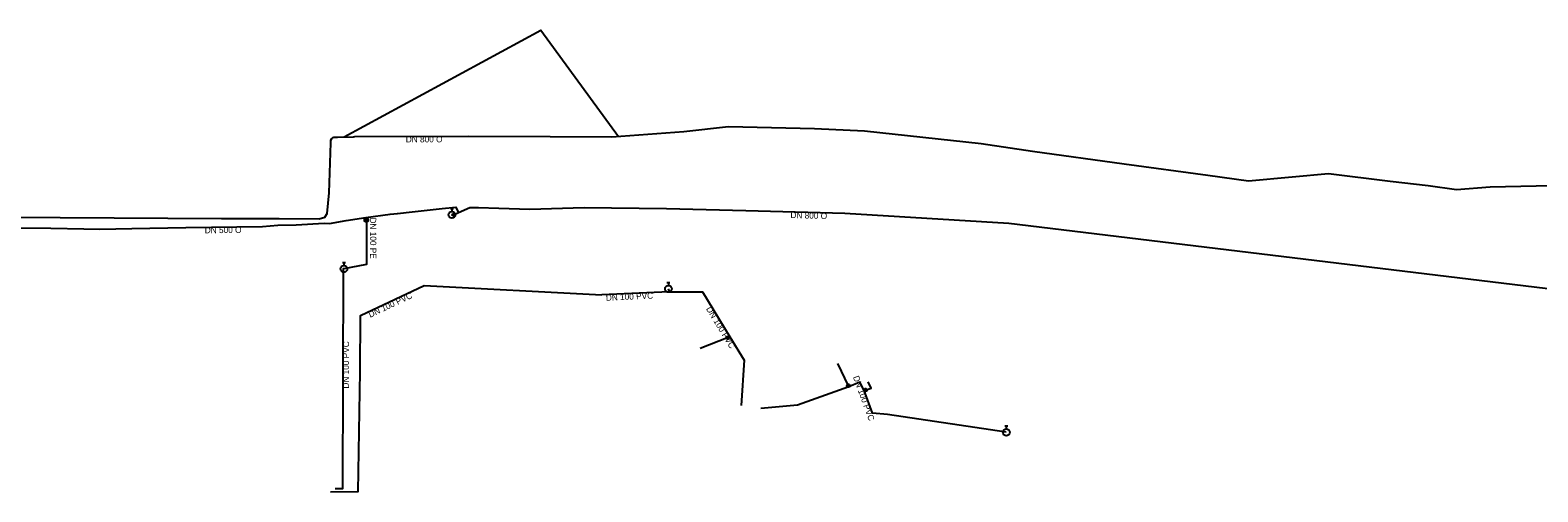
# Model space of a CAD drawing. Extents: x -451355 to -449353, y -1101368 to -1101089.
# Drawn here: x -450137.6 to -449745.7, y -1101299.4 to -1101179.4 of the extents above; entities that cross this region are included whole.
import ezdxf

# ---------------------------------------------------------------- set-up
doc = ezdxf.new("R2010")
doc.units = 0
for name, color, linetype in [('_hydrantova_odbocka_', 7, 'Continuous'), ('_pripojka_prevzato_z_dokumentace_', 7, 'Continuous'), ('_voda_projekt_smvak_', 7, 'Continuous'), ('_voda_smvak_prevzato_z_dokumentace_', 7, 'Continuous'), ('_voda_smvak_priblizne_', 7, 'Continuous'), ('Default', 7, 'Continuous'), ('MoLevel 2', 7, 'Continuous'), ('MoLevel 27', 7, 'Continuous'), ('MoLevel 28', 7, 'Continuous'), ('MoLevel 46', 7, 'Continuous'), ('MoLevel 53', 7, 'Continuous')]:
    doc.layers.add(name, color=color, linetype=linetype)

# ---------------------------------------------------------------- blocks, each defined once
blk = doc.blocks.new('_uzaver_')
at = {"layer": 'Default'}
for p, q in [((-0.000035, -0.000035), (0.000035, 0.000035)), ((0.000035, -0.000035), (-0.000035, 0.000035))]:
    blk.add_line(p, q, dxfattribs=at)
for radius in [0.00005, 0.0000025]:
    blk.add_circle((0, 0), radius, dxfattribs=at)
blk = doc.blocks.new('_uzaver_pripojka_')
at = {"layer": 'Default'}
for p, q in [((-0.000035, -0.000035), (0.000035, 0.000035)), ((0.000035, -0.000035), (-0.000035, 0.000035))]:
    blk.add_line(p, q, dxfattribs=at)
for radius in [0.00005, 0.0000025]:
    blk.add_circle((0, 0), radius, dxfattribs=at)
blk = doc.blocks.new('_hydrant_voda_')
at = {"layer": 'Default'}
for p, q in [((-0.000023, 0.000095), (0.000023, 0.000095)), ((0, 0.000095), (0, 0.00005))]:
    blk.add_line(p, q, dxfattribs=at)
blk.add_circle((0, 0), 0.00005, dxfattribs=at)

msp = doc.modelspace()

# ---------------------------------------------------------------- linework, layer by layer
at = {"layer": '_hydrantova_odbocka_'}
for points in [[(-450027.31, -1101227.36), (-450027.66, -1101227.39), (-450027.98, -1101227.39)], [(-449971.53, -1101247.37), (-449971.54, -1101247.14), (-449971.7, -1101246.64)]]:
    msp.add_lwpolyline(points, dxfattribs=at)
at = {"layer": '_pripojka_prevzato_z_dokumentace_'}
for points in [[(-449955.69, -1101259.11), (-449956.19, -1101259.31), (-449963.41, -1101262.16)], [(-449924.78, -1101272.09), (-449924.92, -1101271.81), (-449927.64, -1101266.02)], [(-449920.77, -1101273.05), (-449920.48, -1101272.96), (-449919.02, -1101272.44), (-449919.73, -1101270.78)]]:
    msp.add_lwpolyline(points, dxfattribs=at)
at = {"layer": '_voda_projekt_smvak_'}
msp.add_lwpolyline([(-450055.98, -1101207.15), (-450004.82, -1101179.37), (-449984.68, -1101207), (-449984.67, -1101207)], dxfattribs=at)
at = {"layer": '_voda_smvak_prevzato_z_dokumentace_'}
for p, q in [((-450026.26, -1101226.9), (-450027.31, -1101227.36)), ((-449971.53, -1101247.37), (-449989.04, -1101248.2))]:
    msp.add_line(p, q, dxfattribs=at)
for points in [[(-450157.79, -1101227.95), (-450087.83, -1101228.34), (-450072.87, -1101228.38), (-450062.45, -1101228.41), (-450060.97, -1101227.97), (-450060.37, -1101227.04), (-450059.89, -1101221.68), (-450059.42, -1101208.64), (-450059.44, -1101207.96), (-450059.16, -1101207.55), (-450058.95, -1101207.32), (-450058.66, -1101207.22), (-450057.69, -1101207.21), (-450053.58, -1101207.08), (-450053.2, -1101207.02), (-450023.78, -1101206.91), (-450002.42, -1101206.98), (-449986.4, -1101207.13), (-449967.71, -1101205.73), (-449956.08, -1101204.38), (-449933.75, -1101204.95), (-449920.75, -1101205.53), (-449890.41, -1101208.81), (-449877.09, -1101210.82), (-449853.21, -1101214.14), (-449831.47, -1101217.07), (-449820.94, -1101218.53), (-449809.59, -1101217.5), (-449800.08, -1101216.65), (-449784.1, -1101218.64), (-449774.23, -1101219.74), (-449766.81, -1101220.78), (-449758.11, -1101220.11), (-449738.15, -1101219.69)], [(-450050.32, -1101228.11), (-450044.02, -1101227.25), (-450042.09, -1101227), (-450038.31, -1101226.62), (-450030.47, -1101225.71), (-450026.99, -1101225.39), (-450026.26, -1101226.9)], [(-449564.49, -1101281.4), (-449698.07, -1101252.11), (-449883.18, -1101229.61), (-449925.88, -1101227.01), (-449951.55, -1101226.31), (-449972.21, -1101225.79), (-449993.64, -1101225.6), (-450007.68, -1101225.99), (-450015.78, -1101225.72), (-450021.06, -1101225.6), (-450023.29, -1101225.59), (-450026.26, -1101226.9)], [(-450157.74, -1101229.56), (-450149.08, -1101230.67), (-450142.79, -1101230.8), (-450132.2, -1101230.86), (-450123.68, -1101231), (-450119.47, -1101231.11), (-450111.15, -1101230.92), (-450097.13, -1101230.65), (-450077.24, -1101230.4), (-450073.21, -1101230.11), (-450068.42, -1101229.99), (-450061.21, -1101229.58), (-450059.76, -1101229.61), (-450055.48, -1101228.82), (-450050.32, -1101228.11)], [(-450056.05, -1101241.44), (-450056.28, -1101241.44), (-450056.38, -1101298.65), (-450058.33, -1101298.58)], [(-450059.5, -1101299.41), (-450052.34, -1101299.3), (-450051.83, -1101268.12), (-450051.73, -1101253.56), (-450035.23, -1101245.8), (-449989.04, -1101248.2)], [(-449971.53, -1101247.37), (-449962.8, -1101247.38), (-449955.69, -1101259.11), (-449952.02, -1101265.19), (-449952.81, -1101276.97)], [(-449883.86, -1101283.92), (-449914.78, -1101279.31), (-449918.64, -1101278.94), (-449920.77, -1101273.05), (-449921.9, -1101270.86), (-449924.78, -1101272.09), (-449938.16, -1101276.83), (-449947.64, -1101277.77)]]:
    msp.add_lwpolyline(points, dxfattribs=at)
at = {"layer": '_voda_smvak_priblizne_'}
msp.add_line((-450050.32, -1101228.11), (-450050.22, -1101228.73), dxfattribs=at)
msp.add_lwpolyline([(-450050.22, -1101228.73), (-450050.18, -1101240.32), (-450056.05, -1101241.44)], dxfattribs=at)

# ---------------------------------------------------------------- block references
at = {"layer": 'MoLevel 27', "xscale": 10000.000000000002, "yscale": 10000, "rotation": -89.5087968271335}
msp.add_blockref('_uzaver_', (-450050.22, -1101228.73), dxfattribs=at)
at = {"layer": 'MoLevel 27', "xscale": 5000, "yscale": 5000}
msp.add_blockref('_uzaver_', (-450027.66, -1101227.39), dxfattribs=at)
at = {"layer": 'MoLevel 28', "xscale": 17636.68430335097, "yscale": 17636.68430335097}
for p in [(-450027.98, -1101227.39), (-450056.05, -1101241.44), (-449971.7, -1101246.64), (-449883.86, -1101283.92)]:
    msp.add_blockref('_hydrant_voda_', p, dxfattribs=at)
at = {"layer": 'MoLevel 53', "xscale": 7999.999999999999, "yscale": 7999.999999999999}
for p in [(-449956.19, -1101259.31), (-449924.92, -1101271.81), (-449920.48, -1101272.96)]:
    msp.add_blockref('_uzaver_pripojka_', p, dxfattribs=at)

# ---------------------------------------------------------------- texts
at = {"layer": 'MoLevel 2'}
msp.add_text('DN 100 PE', height=1.605, rotation=270.1968, dxfattribs=at).set_placement((-450049.26, -1101228.09))
at = {"layer": 'MoLevel 46'}
for s, rotation, p in [('DN 800 O', 0.2175, (-450039.96, -1101208.57)), ('DN 800 O', 358.438, (-449940, -1101228.23)), ('DN 500 O', 0.7201, (-450092.21, -1101232.19)), ('DN 100 PVC', 25.1947, (-450049.22, -1101254.16)), ('DN 100 PVC', 2.7139, (-449987.92, -1101249.75)), ('DN 100 PVC', 301.2217, (-449961.98, -1101251.83)), ('DN 100 PVC', 89.9014, (-450054.73, -1101272.56)), ('DN 100 PVC', 289.8815, (-449923.74, -1101269.56))]:
    msp.add_text(s, height=1.605, rotation=rotation, dxfattribs=at).set_placement(p)

doc.saveas('drawing.dxf')
